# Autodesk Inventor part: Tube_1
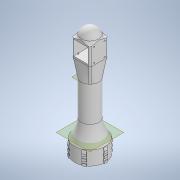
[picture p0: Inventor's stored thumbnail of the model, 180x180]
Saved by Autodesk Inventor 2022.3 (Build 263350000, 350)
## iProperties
Created: 2023-03
Part Number: Tube_1
Material: Generic
Document SubType Name: Modeling
Designer: Manuel Hueso Béjar
Density: 1 g/cm^3
Appearance: Default
Author: Manuel Hueso Béjar
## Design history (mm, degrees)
sketch "Sketch1"
  geometry: C1 r 40 at (0, 0); C2 r 44 at (0, 0); 1 further point
  constraints: 2 centre point, 1 coincident
  dimensions: "d0" = 80 diameter of C1; "d1" = 4 radial gap between concentric circles of C1 C2
extrude "Extrusion1" new body sketch "Sketch1" distance "d2" = 40; taper "d3" = 0 deg
sketch "Sketch2"
  geometry: L1 (44, 40)-(-44, 40) reference; L2 (-44, 40)-(44, 40); L3 (44, 40)-(44, 90); L4 (44, 90)-(-44, 90); L5 (-44, 90)-(-44, 40); L6 (25, 40)-(-25, 40); L7 (-25, 90)-(0, 90); L8 (0, 90)-(0, 240); L9 (0, 240)-(-25, 240); L10 (-25, 240)-(-25, 90); L11 (0, 90)-(0, 40); L12 (0, 40)-(-44, 40); L13 (-25, 240)-(-21, 240); L14 (-21, 240)-(-21, 90); L15 (-21, 90)-(-25, 90); L16 (-25, 90)-(-25, 240); L17 (-40, 40)-(40, 40) reference; A1 r 100 centre (-124.573, 99.228) between (-44, 40) and (-25, 90); A2 r 100 centre (-120.573, 99.228) between (-40, 40) and (-21, 90); 3 further points
  constraints: 30 end point, 6 parallel, 4 perpendicular, 4 point on circle, 3 horizontal, 2 centre point, 2 midpoint, 1 point on line
  dimensions: "d4" = 88 distance of L4.end L3.end; "d5" = 50 distance of L3.end L2.end; "d8" = 100 radius of A1; "d9" = 25 distance of L9.end L8.end; "d10" = 150 distance of L8.end L7.end; "d11" = 4 distance of L14.end L15.end; "d12" = 100 radius of A2; "d79" = 0 distance between parallel lines of L4 L7
revolve "Revolution1" sketch "Sketch2" stored, may be unused: angle "d13" = 90 deg
workplane "Work Plane1"
sketch "Sketch3"
  geometry: L1 (-2.5, -32.5)-(2.5, -32.5); L2 (2.5, -32.5)-(2.5, 32.5); L3 (2.5, 32.5)-(-2.5, 32.5); L4 (-2.5, 32.5)-(-2.5, -32.5); L5 (-2.5, -32.5)-(2.5, 32.5); L6 (2.5, -32.5)-(-2.5, 32.5); L7 (-32.5, -2.5)-(32.5, -2.5); L8 (32.5, -2.5)-(32.5, 2.5); L9 (32.5, 2.5)-(-32.5, 2.5); L10 (-32.5, 2.5)-(-32.5, -2.5); L11 (-32.5, -2.5)-(32.5, 2.5); L12 (32.5, -2.5)-(-32.5, 2.5); C1 r 44 at (0, 0) reference; C2 r 7.5 at (0, 0); C3 r 5 at (0, 0); 9 further points
  constraints: 24 end point, 4 midpoint, 4 parallel, 2 centre point, 2 coincident, 2 horizontal, 2 perpendicular
  dimensions: "d15" = 5 distance of L3.end L2.end; "d16" = 65 distance of L2.end L1.end; "d17" = 65 distance of L9.end L8.end; "d18" = 5 distance of L8.end L7.end; "d19" = 15 diameter of C2; "d20" = 10 diameter of C3
extrude "Extrusion2" join sketch "Sketch3" distance "d21" = 5; taper "d22" = 0 deg
sketch "Sketch4"
  geometry: L1 (-26, -26)-(26, -26); L2 (26, -26)-(26, 26); L3 (26, 26)-(-26, 26); L4 (-26, 26)-(-26, -26); L5 (-26, -26)-(26, 26); L6 (26, -26)-(-26, 26); C1 r 21 at (0, 0) reference; 1 further point
  constraints: 12 end point, 2 midpoint, 2 parallel, 1 horizontal, 1 perpendicular
  dimensions: "d23" = 52 distance of L3.end L2.end; "d24" = 52 distance of L2.end L1.end
extrude "Extrusion3" join sketch "Sketch4" distance "d25" = 5; taper "d26" = 0 deg
workplane "Work Plane2"
sketch "Sketch5"
  geometry: C1 r 25 at (0, 0); 1 further point
  constraints: 1 centre point, 1 coincident
fillet "Fillet1" dims "d28" = 5
loft "Loft1" dims "d29" = 0, "d30" = 90 deg, "d31" = 0, "d32" = 90 deg
  node "Edges1"
sketch "Sketch7"
  geometry: C1 r 5 at (0, 0) reference; C2 r 21 at (0, 0); 1 further point
  constraints: 1 centre point, 1 coincident
extrude "Extrusion4" cut sketch "Sketch7" distance "d33" = 100; taper "d34" = 0 deg
sketch "Sketch11"
  geometry: L1 (-21, -26)-(21, -26) reference; L2 (26, -21)-(26, 21) reference; L3 (21, 26)-(-21, 26) reference; L4 (-26, 21)-(-26, -21) reference; L5 (-21, -21)-(21, -21); L6 (21, -21)-(21, 21); L7 (21, 21)-(-21, 21); L8 (-21, 21)-(-21, -21); L9 (-21, -21)-(21, -21); L10 (21, -21)-(21, -16.5); L11 (21, -16.5)-(-21, -16.5); L12 (-21, -16.5)-(-21, -21); L13 (-21, -16.5)-(21, -16.5); L14 (21, -16.5)-(21, -26); L15 (21, -26)-(-21, -26); L16 (-21, -26)-(-21, -16.5); C1 r 21 at (0, 0) reference; A1 r 5 centre (-21, -21) between (-26, -21) and (-21, -26) reference; A2 r 5 centre (21, -21) between (21, -26) and (26, -21) reference; A3 r 5 centre (21, 21) between (26, 21) and (21, 26) reference; A4 r 5 centre (-21, 21) between (-21, 26) and (-26, 21) reference; A5 r 5 centre (21, -21) between (21, -26) and (26, -21) reference; 8 further points
  constraints: 24 end point, 4 parallel, 2 horizontal, 2 perpendicular, 1 point on circle, 1 point on line, 23 other
  dimensions: "d54" = 5 distance between parallel lines of L4 L8; "d55" = 4.5 distance of L10.end L9.end
  node "Projected Loop2"
extrude "Extrusion7" join sketch "Sketch11" distance "d56" = 5; taper "d57" = 0 deg
extrude "Extrusion8" join sketch "Sketch11" distance "d58" = 45; taper "d59" = 0 deg
sketch "Sketch12"
  geometry: L1 (21, 50)-(21, 5); C1 r 11 at (21, 27.5); 1 further point
  constraints: 2 end point, 1 centre point, 1 midpoint, 1 vertical
  dimensions: "d60" = 45 distance of L1.start L1.end; "d61" = 22 diameter of C1
extrude "Extrusion9" cut sketch "Sketch12" stored distance "d62" = 42; taper "d63" = 0 deg
sketch "Sketch13"
  geometry: L1 (5.5, 12)-(36.5, 12); L2 (36.5, 12)-(36.5, 43); L3 (36.5, 43)-(5.5, 43); L4 (5.5, 43)-(5.5, 12); L5 (5.5, 12)-(36.5, 43); L6 (36.5, 12)-(5.5, 43); C1 r 11 at (21, 27.5) reference; 1 further point
  constraints: 12 end point, 2 midpoint, 2 parallel, 1 horizontal, 1 perpendicular
  dimensions: "d64" = 31 distance of L3.end L2.end; "d65" = 31 distance of L2.end L1.end
hole "Hole2" sketch "Sketch13" at (5.5, 43), (5.5, 12), (36.5, 12), (36.5, 43) diameter "d66" = 2.4; stored, may be unused: countersink angle "d70" = 90 deg, drill point angle "d72" = 0 deg; dims "d67" = 6, "d68" = 4, "d69" = 2, "d71" = 4.2
sketch "Sketch14"
  geometry: L1 (21, 21)-(21, -26) reference; L2 (-21, -26)-(21, -26); L3 (21, -26)-(21, 21); L4 (21, 21)-(-21, 21); L5 (-21, 21)-(-21, -26); 2 further points
  constraints: 8 end point, 2 parallel, 1 horizontal, 1 perpendicular
extrude "Extrusion10" join sketch "Sketch14" distance "d73" = 3; taper "d74" = 0 deg
sketch "Sketch15"
  geometry: L1 (290, 0)-(316, 0); L2 (316, 0)-(316, -26); L3 (316, -26)-(290, -26); L4 (290, -26)-(290, 0); 3 further points
  constraints: 8 end point, 2 parallel, 1 coincident, 1 horizontal, 1 perpendicular, 3 other
  dimensions: "d75" = 26 distance of L2.end L3.end; "d76" = 26 distance of L1.end L2.end
revolve "Revolution2" sketch "Sketch15" stored, may be unused: angle "d77" = 90 deg
fillet "Fillet3" dims "d78" = 10
sketch "Sketch16"
  geometry: L1 (0, 50.068)-(0, 0) reference; L2 (0, 50.068)-(5, 50.068); L3 (5, 50.068)-(5, 45.068); L4 (5, 45.068)-(0, 45.068); L5 (0, 45.068)-(0, 50.068); L6 (0, 0)-(5.292, -50) reference; L7 (0, 0)-(5, 0); L8 (5, 0)-(5, 5.068); L9 (5, 5.068)-(0, 5.068); L10 (0, 5.068)-(0, 0); L11 (5, 45.068)-(35, 45.068); L12 (35, 45.068)-(35, 5.068); L13 (35, 5.068)-(5, 5.068); L14 (5, 5.068)-(5, 45.068); 1 further point
  constraints: 24 end point, 6 parallel, 3 horizontal, 3 perpendicular
  dimensions: "d80" = 5 distance of L3.end L4.end; "d81" = 5 distance of L2.end L3.end; "d82" = 5 distance of L9.end L8.end; "d83" = 5.068 distance of L8.end L7.end; "d102" = 30 distance of L12.end L13.end; "d103" = 40 distance of L11.end L12.end
hole "Hole3" sketch "Sketch16" at (5, 45.068), (5, 5.068), (35, 45.068), (35, 5.068) diameter "d84" = 3.4; stored, may be unused: countersink angle "d88" = 90 deg, drill point angle "d90" = 0 deg; dims "d85" = 6, "d86" = 4.1, "d87" = 5.1, "d89" = 2.2
sketch "Sketch17"
  geometry: L1 (42, 0)-(42, 50.068) reference; L2 (42, 50.068)-(37, 50.068); L3 (37, 50.068)-(37, 45.068); L4 (37, 45.068)-(42, 45.068); L5 (42, 45.068)-(42, 50.068); L6 (42, 0)-(0, 0) reference; L7 (42, 0)-(37, 0); L8 (37, 0)-(37, 5.068); L9 (37, 5.068)-(42, 5.068); L10 (42, 5.068)-(42, 0); L11 (37, 45.068)-(7, 45.068); L12 (7, 45.068)-(7, 5.068); L13 (7, 5.068)-(37, 5.068); L14 (37, 5.068)-(37, 45.068); C1 r 2.05 at (37, 45.068) reference; 1 further point
  constraints: 24 end point, 6 parallel, 3 horizontal, 3 perpendicular
  dimensions: "d91" = 5 distance of L4.end L3.end (derived); "d92" = 5 distance of L3.end L2.end (derived); "d93" = 5 distance of L8.end L9.end; "d94" = 5.068 distance of L7.end L8.end; "d104" = 30 distance of L13.end L12.end; "d105" = 40 distance of L12.end L11.end
hole "Hole4" sketch "Sketch17" at (37, 5.068), (37, 45.068), (7, 45.068), (7, 5.068) diameter "d95" = 3.4; stored, may be unused: countersink angle "d99" = 90 deg, drill point angle "d101" = 0 deg; dims "d96" = 6, "d97" = 4.1, "d98" = 5.1, "d100" = 2.2
sketch "Sketch18"
  geometry: L1 (-42, 5)-(-46, 5); L2 (-46, 5)-(-46, -5); L3 (-46, -5)-(-42, -5); L4 (-42, -5)-(-42, 5); L5 (-42, 5)-(-46, -5); L6 (-46, 5)-(-42, -5); 6 further points
  constraints: 12 end point, 2 midpoint, 2 parallel, 1 coincident, 1 horizontal, 1 horizontal alignment, 1 perpendicular, 4 other
  dimensions: "d106" = 4 distance of L3.end L2.end; "d107" = 10 distance of L2.end L1.end
extrude "Extrusion11" join sketch "Sketch18" distance "d108" = 30; taper "d109" = 0 deg
sketch "Sketch19"
  geometry: L1 (0, 30)-(2.285, 30) reference; L2 (0, 30)-(2.285, 30); L3 (2.285, 30)-(2.285, 40); L4 (2.285, 40)-(0, 40); L5 (0, 40)-(0, 30); L6 (0, 40)-(2.285, 30); 2 further points
  constraints: 10 end point, 2 parallel, 1 horizontal, 1 perpendicular
  dimensions: "d110" = 10 distance of L3.end L2.end
extrude "Extrusion12" join sketch "Sketch19" stored distance "d111" = 30; taper "d112" = 0 deg
pattern_circular "Circular Pattern1" dims angle "d129" = 360 deg
sketch "Sketch20"
  geometry: L1 (-46, 0)-(-43.715, 0) reference; L2 (-46, 0)-(-45, 0); L3 (-45, 0)-(-45, 6); L4 (-45, 6)-(-46, 6); L5 (-46, 6)-(-46, 0); L6 (-46, 6)-(-45, 6); L7 (-45, 6)-(-45, 12); L8 (-45, 12)-(-46, 12); L9 (-46, 12)-(-46, 6); L10 (-46, 12)-(-45, 12); L11 (-45, 12)-(-45, 18); L12 (-45, 18)-(-46, 18); L13 (-46, 18)-(-46, 12); L14 (-46, 18)-(-45, 18); L15 (-45, 18)-(-45, 24); L16 (-45, 24)-(-46, 24); L17 (-46, 24)-(-46, 18); L18 (-46, 24)-(-45, 24); L19 (-45, 24)-(-45, 30); L20 (-45, 30)-(-46, 30); L21 (-46, 30)-(-46, 24); L22 (0, 0)-(0, 10); L23 (0, 0)-(10, 0); L24 (-46, 24)-(-47, 24); L25 (-47, 24)-(-47, 18); L26 (-47, 18)-(-46, 18); L27 (-46, 18)-(-46, 24); L28 (-46, 12)-(-47, 12); L29 (-47, 12)-(-47, 6); L30 (-47, 6)-(-46, 6); L31 (-46, 6)-(-46, 12); 4 further points
  constraints: 60 end point, 14 parallel, 8 horizontal, 8 perpendicular, 1 vertical
  dimensions: "d113" = 1 distance of L4.end L3.end; "d114" = 6 distance of L3.end L2.end; "d115" = 1 distance of L8.end L7.end; "d116" = 6 distance of L7.end L6.end; "d117" = 1 distance of L12.end L11.end; "d118" = 6 distance of L11.end L10.end; "d119" = 1 distance of L16.end L15.end; "d120" = 6 distance of L15.end L14.end; "d121" = 1 distance of L20.end L19.end; "d122" = 6 distance of L19.end L18.end; "d123" = 10 distance of L22.start L22.end; "d124" = 90 deg angle of L23 L22 (derived); "d125" = 1 distance of L26.end L25.end; "d126" = 1 distance of L30.end L29.end
revolve "Revolution3" sketch "Sketch20" stored, may be unused: angle "d127" = 90 deg
body "Solid1"
other parameters: "d14" = -52.5
